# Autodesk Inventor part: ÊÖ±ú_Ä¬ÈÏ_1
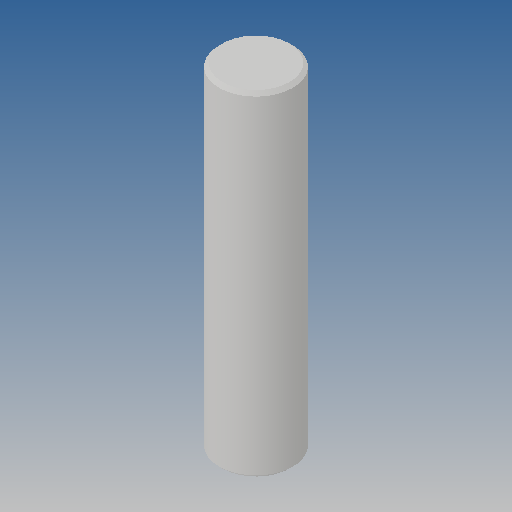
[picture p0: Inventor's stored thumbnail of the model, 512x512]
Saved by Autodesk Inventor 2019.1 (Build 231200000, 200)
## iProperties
Created: 2012-10
Part Number: ÊÖ±ú_Ä¬ÈÏ_1
Material: Ogólny
Document SubType Name: Modeling
Designer: CADENGINEERING4
Density: 1 g/cm^3
Appearance: Domyślna
Author: CADENGINEERING4
Revision Number: ÈÎºÎ
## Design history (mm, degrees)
feature "NONE"
node "Bryła1"
